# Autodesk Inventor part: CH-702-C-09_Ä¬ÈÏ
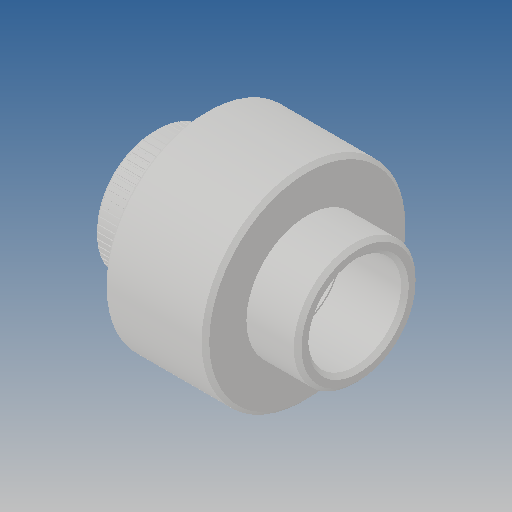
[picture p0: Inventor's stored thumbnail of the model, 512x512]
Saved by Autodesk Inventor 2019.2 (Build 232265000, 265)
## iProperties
Created: 2010-06
Part Number: CH-702-C-09_Ä¬ÈÏ
Material: Ogólny
Document SubType Name: Modeling
Designer: CADENGINEERING4
Density: 1 g/cm^3
Appearance: Domyślna
Author: CADENGINEERING4
Revision Number: ÈÎºÎ
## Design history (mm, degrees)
feature "NONE"
node "Bryła1"
